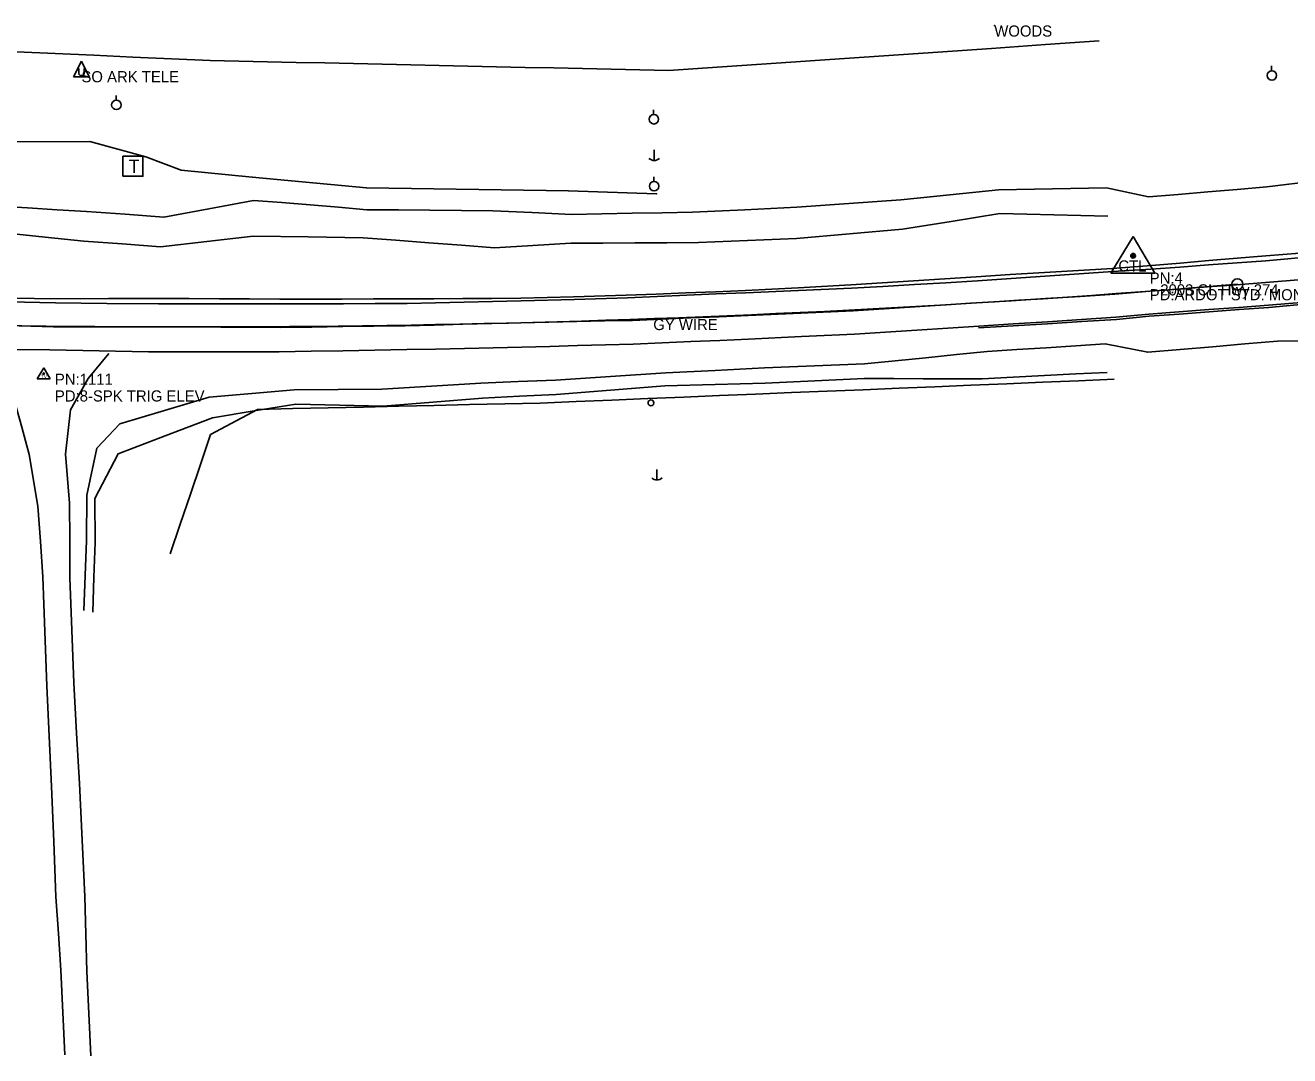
# Model space of a CAD drawing. Extents: x 1138803 to 1169983, y 1655906 to 1658226.
# Drawn here: x 1142177 to 1142745, y 1657285 to 1657748 of the extents above; entities that cross this region are included whole.
import ezdxf

# ---------------------------------------------------------------- set-up
doc = ezdxf.new("R2010")
doc.units = 0
for name, color, linetype in [('S_DITCHLINE', 7, 'Continuous'), ('S_EDGE_PAVEMENT', 7, 'Continuous'), ('S_EXISTING_ALIGNMENT', 7, 'Continuous'), ('S_EXISTING_ALIGNMENT_ANNOT', 7, 'Continuous'), ('S_FIBER_OPTIC_CABLE', 7, 'Continuous'), ('S_GRAVEL_ROAD', 7, 'Continuous'), ('S_MSC_PT_SYM', 7, 'Continuous'), ('S_PAVEMENT_CROWN', 7, 'Continuous'), ('S_PRIMARY_CTL', 7, 'Continuous'), ('S_PRIMARY_CTL_ANNOT', 7, 'Continuous'), ('S_SECONDARY_CTL', 7, 'Continuous'), ('S_SECONDARY_CTL_ANNOT', 7, 'Continuous'), ('S_SHOULDER', 7, 'Continuous'), ('S_SURVEY_TEXT_ANNOT', 7, 'Continuous'), ('S_TELEPHONE_UTILITIES', 7, 'Continuous'), ('S_TREE', 7, 'Continuous'), ('S_UNDERGROUND_CABLE', 7, 'Continuous'), ('S_UTILITY_POLE', 7, 'Continuous'), ('S_UTILITY_POLE_ANNOT', 7, 'Continuous'), ('S_UTL_PT_SYM', 7, 'Continuous')]:
    doc.layers.add(name, color=color, linetype=linetype)

msp = doc.modelspace()

# ---------------------------------------------------------------- linework, layer by layer
at = {"layer": 'S_DITCHLINE'}
for points in [[(1142757.03, 1657678.56), (1142734.73, 1657675.74), (1142721.44, 1657674.62), (1142708.15, 1657673.5), (1142694.86, 1657672.38), (1142681.57, 1657671.26), (1142662.63, 1657675.41), (1142638.38, 1657674.96), (1142614.14, 1657674.5), (1142592.21, 1657672.25), (1142570.27, 1657670.01), (1142546.92, 1657668.31), (1142523.57, 1657666.62), (1142500.11, 1657665.54), (1142476.65, 1657664.46), (1142463.05, 1657664.19), (1142449.45, 1657663.93), (1142435.85, 1657663.66), (1142422.25, 1657663.4), (1142404.59, 1657664.21), (1142386.93, 1657665.03), (1142372.78, 1657665.16), (1142358.64, 1657665.29), (1142344.49, 1657665.42), (1142330.34, 1657665.54), (1142317.59, 1657666.59), (1142304.84, 1657667.64), (1142292.09, 1657668.69), (1142279.34, 1657669.73), (1142259.23, 1657665.94), (1142239.11, 1657662.15), (1142221.72, 1657663.46), (1142204.32, 1657664.76), (1142191.07, 1657665.54), (1142177.83, 1657666.32), (1142164.58, 1657667.1)], [(1142663.23, 1657662.65), (1142638.95, 1657663.2), (1142614.67, 1657663.75), (1142592.85, 1657660.27), (1142571.03, 1657656.8), (1142547.2, 1657654.67), (1142523.37, 1657652.54), (1142501.35, 1657651.66), (1142479.34, 1657650.78), (1142465.01, 1657650.69), (1142450.67, 1657650.6), (1142436.34, 1657650.51), (1142422, 1657650.42), (1142404.82, 1657649.43), (1142387.63, 1657648.44), (1142372.87, 1657649.56), (1142358.1, 1657650.68), (1142343.34, 1657651.8), (1142328.57, 1657652.92), (1142303.88, 1657653.3), (1142279.19, 1657653.68), (1142258.39, 1657651.25), (1142237.6, 1657648.82), (1142220.33, 1657650.12), (1142203.05, 1657651.42), (1142190.11, 1657652.77), (1142177.17, 1657654.11), (1142164.22, 1657655.46)], [(1142761.83, 1657606.77), (1142739.45, 1657606.43), (1142724.89, 1657605.2), (1142710.33, 1657603.97), (1142695.77, 1657602.75), (1142681.22, 1657601.52), (1142662.12, 1657605.25), (1142648.86, 1657604.39), (1142635.61, 1657603.54), (1142622.36, 1657602.68), (1142609.11, 1657601.82), (1142595.32, 1657600.43), (1142581.54, 1657599.03), (1142567.75, 1657597.64), (1142553.97, 1657596.24), (1142531.49, 1657595.36), (1142509.01, 1657594.47), (1142486.83, 1657593.35), (1142464.66, 1657592.23), (1142439.83, 1657590.61), (1142415, 1657589), (1142398.21, 1657588.29), (1142381.43, 1657587.57), (1142359.26, 1657586.25), (1142337.08, 1657584.92), (1142317.36, 1657584.79), (1142297.64, 1657584.67), (1142278.54, 1657582.98), (1142259.44, 1657581.29), (1142239.38, 1657575.34), (1142219.32, 1657569.39), (1142208.93, 1657558.33), (1142204.47, 1657537.34), (1142204.35, 1657516.99), (1142203.7, 1657501.21), (1142203.05, 1657485.44)], [(1142662.92, 1657592.45), (1142648.88, 1657591.73), (1142634.83, 1657591.02), (1142620.78, 1657590.31), (1142606.73, 1657589.6), (1142593.5, 1657589.61), (1142580.26, 1657589.62), (1142567.02, 1657589.63), (1142553.78, 1657589.64), (1142531.52, 1657588.61), (1142509.25, 1657587.58), (1142486.74, 1657586.96), (1142464.23, 1657586.34), (1142439.8, 1657584.44), (1142415.37, 1657582.53), (1142398.81, 1657581.7), (1142382.25, 1657580.86), (1142359.92, 1657579.04), (1142337.59, 1657577.23), (1142317.98, 1657577.7), (1142298.38, 1657578.17), (1142279.65, 1657575.12), (1142260.91, 1657572.08), (1142239.69, 1657563.95), (1142218.46, 1657555.82), (1142208.07, 1657535.86), (1142208.13, 1657516.01), (1142207.64, 1657500.4), (1142207.15, 1657484.78)]]:
    msp.add_lwpolyline(points, dxfattribs=at)
at = {"layer": 'S_EDGE_PAVEMENT'}
for points in [[(1142757.17, 1657644.69), (1142734.28, 1657642.61), (1142721.38, 1657641.65), (1142708.47, 1657640.69), (1142695.57, 1657639.73), (1142682.66, 1657638.77), (1142665.52, 1657637.7), (1142650.31, 1657636.65), (1142635.1, 1657635.6), (1142619.89, 1657634.55), (1142604.68, 1657633.5), (1142590.52, 1657632.7), (1142576.36, 1657631.89), (1142562.2, 1657631.08), (1142548.04, 1657630.28), (1142524.32, 1657629.26), (1142500.6, 1657628.24), (1142487.32, 1657627.66), (1142474.03, 1657627.07), (1142460.75, 1657626.49), (1142447.46, 1657625.91), (1142423.51, 1657625.26), (1142399.55, 1657624.61), (1142386.74, 1657624.31), (1142373.94, 1657624), (1142361.14, 1657623.69), (1142348.34, 1657623.38), (1142334.07, 1657623.35), (1142319.8, 1657623.31), (1142305.53, 1657623.27), (1142291.27, 1657623.24), (1142277.62, 1657623.24), (1142263.97, 1657623.24), (1142250.32, 1657623.24), (1142236.67, 1657623.24), (1142213.49, 1657623.45), (1142190.31, 1657623.66), (1142169.41, 1657624.17)], [(1142759.24, 1657624.64), (1142735.53, 1657622.65), (1142722.07, 1657621.66), (1142708.62, 1657620.66), (1142695.16, 1657619.67), (1142681.71, 1657618.67), (1142666.87, 1657617.3), (1142651.49, 1657616.26), (1142636.1, 1657615.22), (1142620.72, 1657614.18), (1142605.34, 1657613.14), (1142591.35, 1657612.27), (1142577.37, 1657611.41), (1142563.39, 1657610.54), (1142549.41, 1657609.68), (1142525.59, 1657608.53), (1142501.77, 1657607.38), (1142488.83, 1657606.82), (1142475.88, 1657606.26), (1142462.94, 1657605.7), (1142450, 1657605.14), (1142437.48, 1657604.81), (1142424.95, 1657604.48), (1142412.43, 1657604.14), (1142399.91, 1657603.81), (1142387, 1657603.52), (1142374.09, 1657603.23), (1142361.18, 1657602.94), (1142348.27, 1657602.65), (1142333.91, 1657602.42), (1142319.55, 1657602.18), (1142305.19, 1657601.95), (1142290.83, 1657601.72), (1142276.16, 1657601.72), (1142261.49, 1657601.72), (1142246.82, 1657601.72), (1142232.14, 1657601.72), (1142210, 1657602.11), (1142187.85, 1657602.51), (1142167.59, 1657602.72)]]:
    msp.add_lwpolyline(points, dxfattribs=at)
at = {"layer": 'S_EXISTING_ALIGNMENT'}
msp.add_circle((1142721.5, 1657632.02), 2.5, dxfattribs=at)
msp.add_arc((1142252.26, 1663365.55), 5752.69, 267.707455, 274.678683, dxfattribs=at)
at = {"layer": 'S_FIBER_OPTIC_CABLE'}
for p, q in [((1142205.85, 1657696.12), (1142040.24, 1657695.96)), ((1142230.92, 1657689.29), (1142205.85, 1657696.12)), ((1142246.81, 1657683.27), (1142230.92, 1657689.29)), ((1142278.81, 1657680.09), (1142246.81, 1657683.27)), ((1142330.07, 1657675.42), (1142278.81, 1657680.09)), ((1142420.85, 1657673.95), (1142330.07, 1657675.42)), ((1142460.5, 1657672.65), (1142420.85, 1657673.95))]:
    msp.add_line(p, q, dxfattribs=at)
at = {"layer": 'S_GRAVEL_ROAD'}
for points in [[(1142154.33, 1657601.26), (1142161.44, 1657592.63), (1142171.83, 1657580.17), (1142175.18, 1657567.86), (1142178.54, 1657555.56), (1142182.38, 1657532.32), (1142183.56, 1657516.44), (1142184.74, 1657500.56), (1142185.59, 1657476.1), (1142186.43, 1657451.65), (1142187.52, 1657429.02), (1142188.61, 1657406.39), (1142189.59, 1657381.64), (1142190.57, 1657356.89), (1142191.64, 1657340.42), (1142192.7, 1657323.94), (1142193.66, 1657304.9), (1142194.61, 1657285.86)], [(1142214.27, 1657600.98), (1142205, 1657589.75), (1142197.13, 1657575.56), (1142194.8, 1657555.77), (1142196.7, 1657533.64), (1142196.77, 1657516.93), (1142196.85, 1657500.23), (1142197.73, 1657476.6), (1142198.61, 1657452.97), (1142199.84, 1657430.33), (1142201.07, 1657407.69), (1142201.68, 1657395.02), (1142202.3, 1657382.34), (1142202.91, 1657369.66), (1142203.52, 1657356.99), (1142204, 1657340.14), (1142204.47, 1657323.29), (1142205.36, 1657304.38), (1142206.26, 1657285.48)]]:
    msp.add_lwpolyline(points, dxfattribs=at)
at = {"layer": 'S_MSC_PT_SYM'}
for points in [[(1142612.24, 1657748.29), (1142612.24, 1657748.34), (1142612.24, 1657748.29), (1142612.19, 1657748.29), (1142612.24, 1657748.29), (1142612.24, 1657748.24), (1142612.24, 1657748.29), (1142612.29, 1657748.29)], [(1142458.99, 1657616.44), (1142458.99, 1657616.49), (1142458.99, 1657616.44), (1142458.94, 1657616.44), (1142458.99, 1657616.44), (1142458.99, 1657616.39), (1142458.99, 1657616.44), (1142459.04, 1657616.44)]]:
    msp.add_lwpolyline(points, dxfattribs=at)
at = {"layer": 'S_PAVEMENT_CROWN'}
msp.add_lwpolyline([(1142758.09, 1657634.76), (1142734.08, 1657632.76), (1142721.09, 1657631.78), (1142708.09, 1657630.81), (1142695.09, 1657629.83), (1142682.09, 1657628.86), (1142666.37, 1657627.52), (1142650.83, 1657626.55), (1142635.3, 1657625.57), (1142619.76, 1657624.6), (1142604.22, 1657623.62), (1142590.38, 1657622.76), (1142576.53, 1657621.89), (1142562.68, 1657621.02), (1142548.83, 1657620.16), (1142525.24, 1657619.06), (1142501.66, 1657617.96), (1142488.66, 1657617.43), (1142475.66, 1657616.89), (1142462.66, 1657616.35), (1142449.66, 1657615.82), (1142437.13, 1657615.55), (1142424.59, 1657615.29), (1142412.06, 1657615.02), (1142399.52, 1657614.75), (1142386.5, 1657614.41), (1142373.48, 1657614.06), (1142360.46, 1657613.72), (1142347.44, 1657613.37), (1142333.48, 1657613.18), (1142319.53, 1657613), (1142305.57, 1657612.81), (1142291.61, 1657612.62), (1142278.1, 1657612.71), (1142264.59, 1657612.8), (1142251.08, 1657612.89), (1142237.57, 1657612.97), (1142213.54, 1657612.97), (1142189.52, 1657612.97), (1142168.97, 1657613.5)], dxfattribs=at)
at = {"layer": 'S_PRIMARY_CTL'}
for p, q in [((1142674.59, 1657653.53), (1142664.56, 1657637.02)), ((1142674.59, 1657653.53), (1142684.41, 1657637.02)), ((1142664.56, 1657637.02), (1142684.41, 1657637.02))]:
    msp.add_line(p, q, dxfattribs=at)
for radius in [1.04, 0.609, 0.344]:
    msp.add_circle((1142674.59, 1657644.83), radius, dxfattribs=at)
at = {"layer": 'S_SECONDARY_CTL'}
for p, q in [((1142185.08, 1657594.47), (1142182.07, 1657589.52)), ((1142185.08, 1657594.47), (1142188.02, 1657589.52)), ((1142182.07, 1657589.52), (1142188.02, 1657589.52))]:
    msp.add_line(p, q, dxfattribs=at)
for radius in [0.311, 0.183, 0.103]:
    msp.add_circle((1142185.08, 1657591.86), radius, dxfattribs=at)
at = {"layer": 'S_SHOULDER'}
for points in [[(1142757.16, 1657646.66), (1142734.31, 1657644.74), (1142721.45, 1657643.69), (1142708.59, 1657642.64), (1142695.73, 1657641.58), (1142682.87, 1657640.53), (1142665.41, 1657639.17), (1142650.08, 1657638.23), (1142634.76, 1657637.29), (1142619.43, 1657636.35), (1142604.1, 1657635.41), (1142590.03, 1657634.49), (1142575.96, 1657633.56), (1142561.88, 1657632.64), (1142547.81, 1657631.72), (1142524.11, 1657630.44), (1142500.41, 1657629.16), (1142487.02, 1657628.65), (1142473.63, 1657628.13), (1142460.24, 1657627.62), (1142446.86, 1657627.1), (1142423.18, 1657626.45), (1142399.51, 1657625.79), (1142386.47, 1657625.7), (1142373.43, 1657625.61), (1142360.39, 1657625.51), (1142347.35, 1657625.42), (1142333.3, 1657625.41), (1142319.25, 1657625.4), (1142305.21, 1657625.4), (1142291.16, 1657625.39), (1142277.6, 1657625.45), (1142264.04, 1657625.51), (1142250.48, 1657625.57), (1142236.92, 1657625.63), (1142214.13, 1657625.56), (1142191.33, 1657625.49), (1142170.42, 1657625.78)], [(1142759.37, 1657623.84), (1142735.65, 1657621.63), (1142722.21, 1657620.63), (1142708.76, 1657619.64), (1142695.32, 1657618.64), (1142681.87, 1657617.65), (1142667.1, 1657616.18), (1142651.62, 1657615.25), (1142636.13, 1657614.32), (1142620.65, 1657613.39), (1142605.16, 1657612.47)]]:
    msp.add_lwpolyline(points, dxfattribs=at)
at = {"layer": 'S_TELEPHONE_UTILITIES'}
msp.add_lwpolyline([(1142220.66, 1657680.53), (1142220.66, 1657689.53), (1142229.66, 1657689.53), (1142229.66, 1657680.53)], close=True, dxfattribs=at)
at = {"layer": 'S_TREE'}
for points in [[(1142172.79, 1657736.46), (1142190.21, 1657735.68), (1142207.63, 1657734.9), (1142225.05, 1657734.12), (1142242.47, 1657733.34), (1142259.89, 1657732.56), (1142272.76, 1657732.28), (1142285.63, 1657732), (1142298.5, 1657731.72), (1142311.36, 1657731.44), (1142324.23, 1657731.16), (1142337.1, 1657730.87), (1142349.97, 1657730.59), (1142362.84, 1657730.31), (1142375.7, 1657730.03), (1142388.57, 1657729.75), (1142401.44, 1657729.47), (1142414.31, 1657729.19), (1142427.18, 1657728.9), (1142440.05, 1657728.62), (1142452.91, 1657728.34), (1142465.78, 1657728.06), (1142489.99, 1657729.72), (1142514.2, 1657731.38), (1142538.4, 1657733.03), (1142562.61, 1657734.69), (1142586.81, 1657736.35), (1142611.02, 1657738.01), (1142635.23, 1657739.67), (1142659.43, 1657741.33)], [(1142241.83, 1657510.94), (1142246.39, 1657524.33), (1142250.95, 1657537.72), (1142255.51, 1657551.11), (1142260.08, 1657564.51), (1142281.07, 1657575.8), (1142296.96, 1657576.16), (1142312.84, 1657576.52), (1142328.73, 1657576.87), (1142344.61, 1657577.23), (1142360.5, 1657577.59), (1142376.39, 1657577.95), (1142392.27, 1657578.3), (1142408.16, 1657578.66), (1142424.29, 1657579.33), (1142440.41, 1657580), (1142456.54, 1657580.67), (1142472.66, 1657581.33), (1142488.79, 1657582), (1142504.92, 1657582.67), (1142521.04, 1657583.34), (1142537.17, 1657584), (1142553.3, 1657584.67), (1142569.42, 1657585.34), (1142585.55, 1657586.01), (1142601.67, 1657586.67), (1142617.8, 1657587.34), (1142633.93, 1657588.01), (1142650.05, 1657588.68), (1142666.18, 1657589.34)]]:
    msp.add_lwpolyline(points, dxfattribs=at)
at = {"layer": 'S_UNDERGROUND_CABLE'}
for p, q in [((1142202.02, 1657732.3), (1142198.49, 1657725.21)), ((1142200.82, 1657726.45), (1142200.82, 1657728.89)), ((1142202.02, 1657732.3), (1142205.51, 1657725.21)), ((1142203.18, 1657728.89), (1142203.18, 1657726.45)), ((1142198.49, 1657725.21), (1142205.51, 1657725.21)), ((1142201.44, 1657725.79), (1142200.82, 1657726.45)), ((1142202.64, 1657725.79), (1142201.44, 1657725.79)), ((1142203.18, 1657726.45), (1142202.64, 1657725.79))]:
    msp.add_line(p, q, dxfattribs=at)
at = {"layer": 'S_UTILITY_POLE'}
for p, q in [((1142736.87, 1657727.98), (1142736.87, 1657730.09)), ((1142217.59, 1657714.76), (1142217.59, 1657716.87)), ((1142459.14, 1657708.28), (1142459.14, 1657710.39)), ((1142459.36, 1657692.35), (1142459.36, 1657687.63)), ((1142459.25, 1657678.24), (1142459.25, 1657680.35)), ((1142460.55, 1657548.87), (1142460.55, 1657544.14))]:
    msp.add_line(p, q, dxfattribs=at)
for centre, radius in [((1142737, 1657725.84), 2.13), ((1142217.71, 1657712.62), 2.13), ((1142459.26, 1657706.14), 2.13), ((1142459.37, 1657676.1), 2.13), ((1142457.95, 1657578.74), 1.31)]:
    msp.add_circle(centre, radius, dxfattribs=at)
for centre in [(1142459.42, 1657691.05), (1142460.62, 1657547.57)]:
    msp.add_arc(centre, 3.41, 226.3972, 313.6028, dxfattribs=at)
at = {"layer": 'S_UTL_PT_SYM'}
for points in [[(1142205.85, 1657696.12), (1142205.85, 1657696.17), (1142205.85, 1657696.12), (1142205.8, 1657696.12), (1142205.85, 1657696.12), (1142205.85, 1657696.07), (1142205.85, 1657696.12), (1142205.9, 1657696.12)], [(1142230.92, 1657689.29), (1142230.92, 1657689.34), (1142230.92, 1657689.29), (1142230.87, 1657689.29), (1142230.92, 1657689.29), (1142230.92, 1657689.24), (1142230.92, 1657689.29), (1142230.97, 1657689.29)], [(1142246.81, 1657683.27), (1142246.81, 1657683.32), (1142246.81, 1657683.27), (1142246.76, 1657683.27), (1142246.81, 1657683.27), (1142246.81, 1657683.22), (1142246.81, 1657683.27), (1142246.86, 1657683.27)], [(1142278.81, 1657680.09), (1142278.81, 1657680.14), (1142278.81, 1657680.09), (1142278.76, 1657680.09), (1142278.81, 1657680.09), (1142278.81, 1657680.04), (1142278.81, 1657680.09), (1142278.86, 1657680.09)], [(1142330.07, 1657675.42), (1142330.07, 1657675.47), (1142330.07, 1657675.42), (1142330.02, 1657675.42), (1142330.07, 1657675.42), (1142330.07, 1657675.37), (1142330.07, 1657675.42), (1142330.12, 1657675.42)], [(1142420.85, 1657673.95), (1142420.85, 1657674), (1142420.85, 1657673.95), (1142420.8, 1657673.95), (1142420.85, 1657673.95), (1142420.85, 1657673.9), (1142420.85, 1657673.95), (1142420.9, 1657673.95)], [(1142460.5, 1657672.65), (1142460.5, 1657672.7), (1142460.5, 1657672.65), (1142460.45, 1657672.65), (1142460.5, 1657672.65), (1142460.5, 1657672.6), (1142460.5, 1657672.65), (1142460.55, 1657672.65)], [(1142458.99, 1657616.44), (1142458.99, 1657616.49), (1142458.99, 1657616.44), (1142458.94, 1657616.44), (1142458.99, 1657616.44), (1142458.99, 1657616.39), (1142458.99, 1657616.44), (1142459.04, 1657616.44)]]:
    msp.add_lwpolyline(points, dxfattribs=at)

# ---------------------------------------------------------------- texts
at = {"layer": 'S_EXISTING_ALIGNMENT_ANNOT'}
msp.add_text('2003 CL Hwy 274', height=5, dxfattribs=at).set_placement((1142686.83, 1657627.02))
at = {"layer": 'S_PRIMARY_CTL'}
msp.add_text('CTL', height=5, rotation=360, dxfattribs=at).set_placement((1142668, 1657637.76))
at = {"layer": 'S_PRIMARY_CTL_ANNOT'}
for s, p in [('PN:4', (1142682.09, 1657632.33)), ('PD:ARDOT STD. MON. STAMPED PN:4', (1142682.09, 1657624.83))]:
    msp.add_text(s, height=5, dxfattribs=at).set_placement(p)
at = {"layer": 'S_SECONDARY_CTL'}
msp.add_text('TV', height=1.5, rotation=360, dxfattribs=at).set_placement((1142183.87, 1657589.85))
at = {"layer": 'S_SECONDARY_CTL_ANNOT'}
for s, p in [('PN:1111', (1142190.08, 1657586.86)), ('PD:8-SPK TRIG ELEV', (1142190.08, 1657579.36))]:
    msp.add_text(s, height=5, dxfattribs=at).set_placement(p)
at = {"layer": 'S_SURVEY_TEXT_ANNOT'}
for s, p in [('WOODS', (1142612.24, 1657743.29)), ('GY WIRE', (1142458.99, 1657611.44))]:
    msp.add_text(s, height=5, dxfattribs=at).set_placement(p)
at = {"layer": 'S_TELEPHONE_UTILITIES'}
msp.add_text('T', height=6, rotation=360, dxfattribs=at).set_placement((1142223.23, 1657682.03))
at = {"layer": 'S_UTILITY_POLE_ANNOT'}
msp.add_text('SO ARK TELE', height=5, dxfattribs=at).set_placement((1142202.02, 1657722.77))

doc.saveas('drawing.dxf')
